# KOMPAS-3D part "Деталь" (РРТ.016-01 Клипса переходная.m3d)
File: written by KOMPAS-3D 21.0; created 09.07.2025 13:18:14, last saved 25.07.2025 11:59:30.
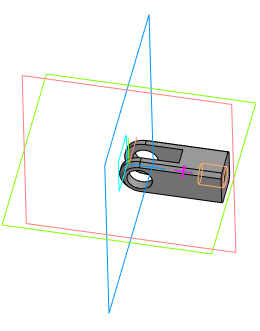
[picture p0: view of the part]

Document properties: Автор: User; Полное имя файла: C:\Users\User\Desktop\Ручной ротатор КД\Модели КД\РРТ.016-01 Клипса переходная.m3d

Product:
- Part/product: Деталь
    Масса: 0.009717
    Форматы листов документа: A4

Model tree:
1. Эскиз:1
2. Элемент выдавливания:1
     Расстояние 1 = 23; Расстояние 2 = 1.5
3. Эскиз:2  (with: Элемент выдавливания:1)
4. Эскиз:3
5. Эскиз:4  (with: Элемент выдавливания:1)
6. Элемент выдавливания:3
     Расстояние 2 = 10
7. Скругление:1  (with: Элемент выдавливания:1)
     Радиус = 5
8. Касательная плоскость:1  (with: Скругление:1)
9. Эскиз:5
10. Элемент выдавливания:4
     Расстояние 2 = 14
11. Отверстие:3  (with: Элемент выдавливания:1)  (labels: M5)
     Глубина выреза = 8; Диаметр отверстия = 4.13397; Угол конуса дна = 118; Расстояние 1 = 4.5; Расстояние 2 = 5
12. M5  (with: Элемент выдавливания:1)  (labels: M5; cil0_24705-2004 coarse)
     Длина резьбы = 6; Шаг резьбы = 0.8; Номинальный диаметр резьбы = 5
13. Фаска:1  (with: Отверстие:3)
     Угол = 45; Длина 1 = 0.5; Длина 2 = 0.5
14. Фаска:6  (with: Элемент выдавливания:1)
     Угол = 45; Длина 1 = 1; Длина 2 = 1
